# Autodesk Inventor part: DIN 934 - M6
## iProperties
Comments: To add or edit properties for Autodesk Inventor files, use iProperties.
Created: 2004-02
Part Number: DIN 934 - M6
Vendor: Autodesk Inc.
Document SubType Name: Modeling
Designer: Administrator
Material: A4
Description: Sechskantmutter
Standard: DIN 934
Manufacturer: Standard
Standards Organization: Custom
Alert: To add or edit properties for Autodesk Inventor files, use iProperties.
Control State: 0
Master: False
Checked Out: False
Shininess: 64.0
Length Units: 11269
Angle Units: 11279
Time Units: 11290
Mass Units: 11283
Length Display Precision: 3
Angle Display Precision: 2
Compacted: True
EGR: 1
Classification: un/spsc 31161727
ArtNr: L29830
Farbe: Metal-Steel
Zuschnitt: 5mm
GesGewicht: 0,0kg
Zeichnungsnummer: DIN 934 - M6
Density: 0.0
Volumn: 0.0
Area: 0.0
PropertySet Name: Model Information
Author: Administrator
Revision Number: 5
Title: Sechskantmutter M6
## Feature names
1. Körper [Extrusion]
2. Fase1 [Revolution]
3. Gewinde [Hole]
4. Fase2 [Chamfer]
5. Fase3 [Chamfer]
